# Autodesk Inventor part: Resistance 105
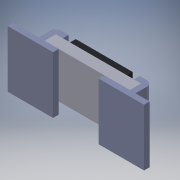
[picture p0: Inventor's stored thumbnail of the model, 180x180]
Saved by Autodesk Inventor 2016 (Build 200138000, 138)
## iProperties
Created: 2018-03
Part Number: Resistance 105
Material: Générique
Document SubType Name: Modeling
Designer: Bruno
Density: 1 g/cm^3
Appearance: Par défaut
Author: Bruno
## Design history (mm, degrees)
feature "Composite1"
body "Srf1"
